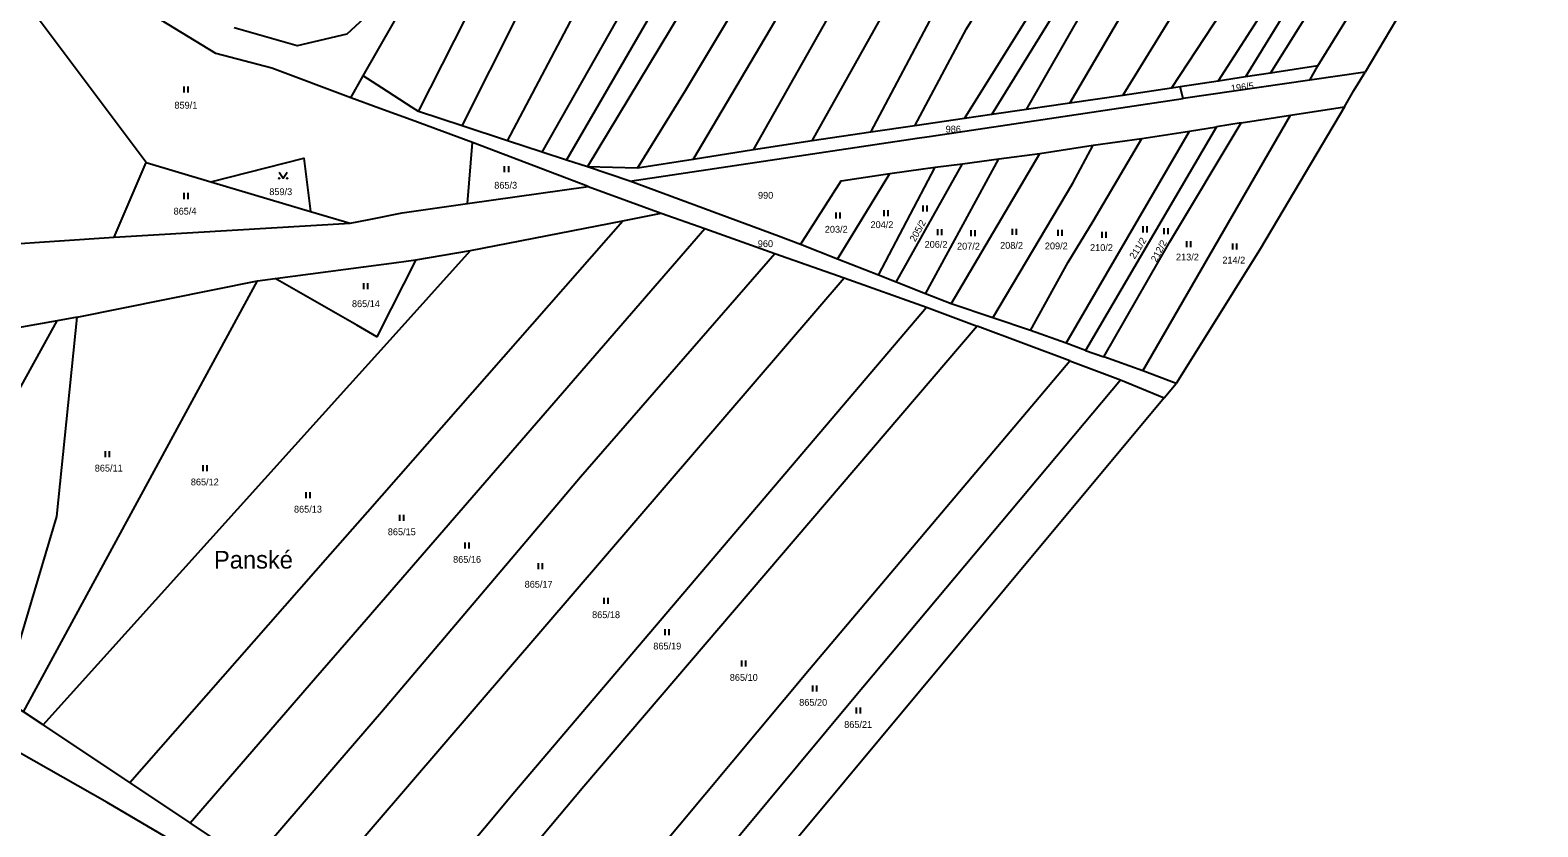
# Model space of a CAD drawing. Extents: x -751333 to -746055, y -1133395 to -1129777.
# Drawn here: x -747223.3 to -746848.3, y -1131915.2 to -1131717 of the extents above; entities that cross this region are included whole.
import ezdxf

# ---------------------------------------------------------------- set-up
doc = ezdxf.new("R2010")
doc.units = 0
for name, color, linetype in [('Hranice parcel', 7, 'Continuous'), ('Parcelní čísla', 7, 'Continuous'), ('Pop  PČ popisy', 7, 'Continuous'), ('Značky kultur', 7, 'Continuous')]:
    doc.layers.add(name, color=color, linetype=linetype)

msp = doc.modelspace()

# ---------------------------------------------------------------- linework, layer by layer
at = {"layer": 'Hranice parcel'}
for p, q in [((-747140.43, -1131728.4), (-747107.8, -1131671.12)), ((-747143.51, -1131733.86), (-747140.43, -1131728.4)), ((-746921.02, -1131728.67), (-746927.75, -1131729.7)), ((-746914.77, -1131727.71), (-746921.02, -1131728.67)), ((-746902.98, -1131725.91), (-746914.77, -1131727.71)), ((-746904.95, -1131729.44), (-746902.98, -1131725.91)), ((-746891.21, -1131727.46), (-746904.95, -1131729.44)), ((-746939.41, -1131731.47), (-746951.49, -1131733.25)), ((-746937.21, -1131731.15), (-746939.41, -1131731.47)), ((-746927.75, -1131729.7), (-746937.21, -1131731.15)), ((-746936.48, -1131734), (-746937.21, -1131731.15)), ((-746904.95, -1131729.44), (-746936.48, -1131734)), ((-746951.49, -1131733.25), (-746964.66, -1131735.18)), ((-746909.81, -1131738.2), (-746896.34, -1131736.09)), ((-747115.85, -1131740.82), (-747126.73, -1131737.25)), ((-746990.85, -1131739.02), (-747003.2, -1131740.83)), ((-746984.07, -1131738.03), (-746990.85, -1131739.02)), ((-746975.44, -1131736.76), (-746984.07, -1131738.03)), ((-746946.5, -1131801.74), (-746909.81, -1131738.2)), ((-746922.05, -1131740.11), (-746928.22, -1131741.07)), ((-746922.05, -1131740.11), (-746909.81, -1131738.2)), ((-747104.57, -1131744.53), (-747115.85, -1131740.82)), ((-747014.2, -1131742.44), (-747028.78, -1131744.58)), ((-747003.2, -1131740.83), (-747014.2, -1131742.44)), ((-746965.61, -1131794.89), (-746934.95, -1131742.12)), ((-746928.22, -1131741.07), (-746960.81, -1131796.68)), ((-746946.77, -1131743.96), (-746934.95, -1131742.12)), ((-746934.95, -1131742.12), (-746928.22, -1131741.07)), ((-747114.55, -1131760.12), (-747113.28, -1131744.96)), ((-747084.49, -1131755.95), (-747113.28, -1131744.96)), ((-747095.98, -1131747.35), (-747104.57, -1131744.53)), ((-747089.88, -1131749.36), (-747095.98, -1131747.35)), ((-747043.35, -1131746.83), (-747058.42, -1131749.2)), ((-747028.78, -1131744.58), (-747043.35, -1131746.83)), ((-746972.15, -1131747.7), (-746958.91, -1131745.66)), ((-746958.91, -1131745.66), (-746946.77, -1131743.96)), ((-747202.38, -1131768.48), (-747194.42, -1131749.94)), ((-747194.42, -1131749.94), (-747178.35, -1131754.73)), ((-747084.67, -1131751), (-747089.88, -1131749.36)), ((-747074.14, -1131754.55), (-747084.67, -1131751)), ((-747072.25, -1131751.38), (-747084.67, -1131751)), ((-747058.42, -1131749.2), (-747072.25, -1131751.38)), ((-747012.31, -1131777.98), (-746998.16, -1131751.1)), ((-747007.84, -1131779.73), (-746991.41, -1131750.26)), ((-747000.55, -1131782.6), (-746982.37, -1131749)), ((-746998.16, -1131751.1), (-746991.41, -1131750.26)), ((-746994.24, -1131785.11), (-746972.15, -1131747.7)), ((-746991.41, -1131750.26), (-746982.37, -1131749)), ((-746982.37, -1131749), (-746972.15, -1131747.7)), ((-747178.35, -1131754.73), (-747153.61, -1131762.1)), ((-747022.48, -1131773.99), (-747009.45, -1131752.7)), ((-747114.55, -1131760.12), (-747084.49, -1131755.95)), ((-747084.49, -1131755.95), (-747066.3, -1131762.59)), ((-747153.61, -1131762.1), (-747143.72, -1131765.05)), ((-747075.87, -1131764.45), (-747066.3, -1131762.59)), ((-747066.3, -1131762.59), (-747055.5, -1131766.4)), ((-747202.38, -1131768.48), (-747143.72, -1131765.05)), ((-747113.75, -1131771.83), (-747075.87, -1131764.45)), ((-747055.5, -1131766.4), (-747038.09, -1131772.55)), ((-747127.4, -1131774.15), (-747113.75, -1131771.83)), ((-747038.09, -1131772.55), (-747020.83, -1131778.66)), ((-747022.48, -1131773.99), (-747031.69, -1131770.37)), ((-747012.31, -1131777.98), (-747022.48, -1131773.99)), ((-747224.99, -1131886.58), (-747166.79, -1131779.35)), ((-747211.65, -1131788.43), (-747166.79, -1131779.35)), ((-747166.79, -1131779.35), (-747162.4, -1131778.78)), ((-747020.83, -1131778.66), (-747000.3, -1131785.93)), ((-747007.84, -1131779.73), (-747012.31, -1131777.98)), ((-747000.55, -1131782.6), (-747007.84, -1131779.73)), ((-746994.24, -1131785.11), (-747000.55, -1131782.6)), ((-746983.84, -1131788.6), (-746994.24, -1131785.11)), ((-747211.65, -1131788.43), (-747216.62, -1131789.31)), ((-747000.3, -1131785.93), (-746987.72, -1131790.65)), ((-746974.46, -1131791.75), (-746983.84, -1131788.6)), ((-747229.61, -1131813), (-747216.62, -1131789.31)), ((-746964.65, -1131799.29), (-746987.72, -1131790.65)), ((-746965.61, -1131794.89), (-746974.46, -1131791.75)), ((-746960.81, -1131796.68), (-746965.61, -1131794.89)), ((-746931.04, -1131793.38), (-746938.23, -1131804.89)), ((-746964.65, -1131799.29), (-746952.09, -1131804)), ((-746960.81, -1131796.68), (-746956.26, -1131798.27)), ((-746946.5, -1131801.74), (-746956.26, -1131798.27)), ((-746938.23, -1131804.89), (-746946.5, -1131801.74)), ((-746952.09, -1131804), (-746941.23, -1131808.49)), ((-746941.23, -1131808.49), (-746938.23, -1131804.89)), ((-746941.23, -1131808.49), (-747020.64, -1131903.85)), ((-747220.07, -1131889.85), (-747224.99, -1131886.58)), ((-747198.55, -1131904.18), (-747220.07, -1131889.85)), ((-747183.54, -1131914.17), (-747198.55, -1131904.18)), ((-747168.35, -1131924.28), (-747183.54, -1131914.17))]:
    msp.add_line(p, q, dxfattribs=at)
for points in [[(-747115.85, -1131740.82), (-747101.98, -1131713.33), (-747085.53, -1131682.34), (-747070.66, -1131651.81), (-747069.92, -1131650.29), (-747060.11, -1131630.3), (-747055.87, -1131622.19), (-747047.5, -1131606.16), (-747025.18, -1131564.19), (-746984.84, -1131493.86), (-746972.78, -1131477.2), (-746949.19, -1131444.14), (-746924.52, -1131406.32), (-746891.3, -1131355.07), (-746872.46, -1131327.44)], [(-747104.57, -1131744.53), (-747074.01, -1131686.66), (-747062.86, -1131663.99), (-747044.55, -1131625.9), (-747038.23, -1131613.87), (-747033.2, -1131604.29), (-747020.87, -1131581.25), (-747014.2, -1131568.8), (-746980.89, -1131511.72), (-746959.19, -1131477.95), (-746938.3, -1131445.7), (-746906.3, -1131397.79), (-746880.95, -1131356.37), (-746864.98, -1131331.78)], [(-747095.98, -1131747.35), (-747074.34, -1131709.19), (-747062.94, -1131688.91), (-747054.44, -1131671.18), (-747030.22, -1131622.02), (-747003.78, -1131573.59), (-746999.79, -1131566.27), (-746985.12, -1131541.69), (-746979.78, -1131532.75), (-746975.21, -1131525.11), (-746953.97, -1131491.61), (-746897.43, -1131402.02), (-746856.2, -1131336.86)], [(-747089.88, -1131749.36), (-747056.78, -1131692.26), (-747040.44, -1131657.76), (-747010.02, -1131596.06), (-746982.14, -1131547.97), (-746977.6, -1131540.14), (-746952.97, -1131500.95), (-746943.76, -1131486.29), (-746932.5, -1131468.46), (-746900.9, -1131419.92), (-746886.76, -1131396.86), (-746861.19, -1131356.24), (-746848.88, -1131337.27)], [(-747084.67, -1131751), (-747056.2, -1131703.86), (-747037.38, -1131665.4), (-747027.75, -1131645.14), (-747010.19, -1131608.84), (-747001.37, -1131592.36), (-746984.88, -1131564.32), (-746959.67, -1131522.76), (-746955.95, -1131516.9), (-746940.13, -1131491.96), (-746923.29, -1131465.74), (-746918.73, -1131458.64), (-746886.86, -1131408.57), (-746872, -1131384.8), (-746844.5, -1131337.51)], [(-747072.25, -1131751.38), (-747060.28, -1131732), (-747039.59, -1131697.38), (-747028.61, -1131673.06), (-747010.61, -1131638.67), (-746991.07, -1131601.65), (-746978.19, -1131579.68), (-746954.07, -1131538.52), (-746930.93, -1131499.45), (-746914.81, -1131473.69), (-746900.96, -1131451.69), (-746895.63, -1131443.23), (-746877.35, -1131414.14), (-746871.32, -1131404.39), (-746861.32, -1131388.21), (-746832.31, -1131338.23)], [(-747058.42, -1131749.2), (-747038.09, -1131714.85), (-747017.02, -1131676.4), (-746987.05, -1131621.46), (-746963.1, -1131578.77), (-746922.22, -1131508.08), (-746895.58, -1131462.61), (-746885.22, -1131445.58), (-746861.28, -1131407.04), (-746857.11, -1131399.99), (-746832.67, -1131358.76), (-746821.13, -1131339.58)], [(-747043.35, -1131746.83), (-747012.7, -1131692.42), (-747004.53, -1131676.4), (-746988.51, -1131647.63), (-746951.39, -1131581.85), (-746924.23, -1131534.57), (-746904.03, -1131500.8), (-746883.99, -1131466.86), (-746842.36, -1131398.13), (-746824.55, -1131367.37), (-746811.66, -1131346), (-746808.72, -1131341.12)], [(-747028.78, -1131744.58), (-747015.65, -1131721.17), (-746994.33, -1131683.03), (-746980.83, -1131659.61), (-746963.82, -1131630.88), (-746947.17, -1131601.52), (-746919.98, -1131553.97), (-746908.36, -1131532.89), (-746893.15, -1131504.79), (-746883.53, -1131486.51), (-746871.73, -1131466.88), (-746842.83, -1131420.22), (-746814.47, -1131369.41), (-746798.54, -1131343.8)], [(-747014.2, -1131742.44), (-746998.02, -1131711.91), (-746986.84, -1131694.8), (-746954.43, -1131638.96), (-746913.55, -1131568.61), (-746875.82, -1131496.38), (-746844.04, -1131445.67), (-746820.17, -1131403.25), (-746804.23, -1131373.45), (-746788.13, -1131346.53)], [(-747003.2, -1131740.83), (-746990.36, -1131716.69), (-746969.83, -1131683.37), (-746954.44, -1131658.33), (-746938.41, -1131630.76), (-746907.08, -1131576), (-746881.78, -1131529.17), (-746860.71, -1131491.16), (-746828.65, -1131435.77), (-746803.15, -1131391.01), (-746779.33, -1131348.85)], [(-746990.85, -1131739.02), (-746967.01, -1131700.7), (-746944.49, -1131660.79), (-746927.2, -1131631.17), (-746901.46, -1131584.95), (-746872.72, -1131533.26), (-746835.26, -1131467.04), (-746805.54, -1131414.43), (-746786.36, -1131381.65), (-746769.23, -1131352.27)], [(-746984.07, -1131738.03), (-746956.76, -1131693.62), (-746930.93, -1131647.96), (-746900.47, -1131595.76), (-746868.27, -1131537.95), (-746830.68, -1131470.71), (-746810.85, -1131435.82), (-746776.73, -1131375.73), (-746764.19, -1131354.41)], [(-746975.44, -1131736.76), (-746951.32, -1131694.53), (-746914.93, -1131630.57), (-746896.94, -1131599.81), (-746888.97, -1131584.23), (-746874.92, -1131559.39), (-746854.79, -1131524.52), (-746827.75, -1131476.66), (-746792.97, -1131415.79), (-746773.98, -1131382.51), (-746758.48, -1131357.76)], [(-746964.66, -1131735.18), (-746937.82, -1131689.24), (-746909.87, -1131639.48), (-746895.97, -1131615.54), (-746872.27, -1131573.98), (-746850.31, -1131536.07), (-746831.17, -1131502.49), (-746808.23, -1131462.22), (-746792.36, -1131433.87), (-746763.35, -1131382.36), (-746749.89, -1131362.79)], [(-746951.49, -1131733.25), (-746931.91, -1131701.47), (-746888.6, -1131625.72), (-746854.73, -1131563.34), (-746833.09, -1131523.91), (-746818.81, -1131499.06), (-746785.31, -1131439.88), (-746759.87, -1131395.96), (-746741.44, -1131367.75)], [(-746939.41, -1131731.47), (-746922.78, -1131706.16), (-746885.19, -1131638.39), (-746862.7, -1131598.42), (-746843.79, -1131566.28), (-746817.59, -1131520.32), (-746790.54, -1131471.76), (-746755.61, -1131410.4), (-746732.32, -1131373.1)], [(-746927.75, -1131729.7), (-746911.51, -1131704.41), (-746890.72, -1131669.08), (-746852.43, -1131600.31), (-746825.91, -1131552.9), (-746799.17, -1131506.71), (-746783.9, -1131480.65), (-746743.56, -1131407.78), (-746725.23, -1131377.02)], [(-746719.96, -1131379.93), (-746754.34, -1131438.63), (-746789.74, -1131501.01), (-746804.77, -1131526.77), (-746817.08, -1131549.42), (-746845.95, -1131600.18), (-746871.48, -1131645.69), (-746889.1, -1131676.85), (-746895.02, -1131686.35), (-746921.02, -1131728.67)], [(-746914.77, -1131727.71), (-746899.96, -1131704.06), (-746890.46, -1131686.35), (-746873.6, -1131657.79), (-746841.77, -1131601.25), (-746803.56, -1131534.6), (-746785.77, -1131503.44), (-746759.79, -1131458.77), (-746727.58, -1131402.99), (-746716.03, -1131382.11)], [(-746902.98, -1131725.91), (-746875.56, -1131681.48), (-746856.95, -1131647.82), (-746831.81, -1131603.9), (-746823.76, -1131588.48), (-746792.61, -1131535.89), (-746783.34, -1131518.48), (-746771.27, -1131499.19), (-746735.03, -1131436.04), (-746706.95, -1131387.13)], [(-746698.14, -1131392), (-746721.13, -1131432.18), (-746762.97, -1131504.51), (-746805.6, -1131577.83), (-746835.31, -1131629.56), (-746853.4, -1131661.11), (-746880.17, -1131708.85), (-746891.21, -1131727.46)], [(-747126.73, -1131737.25), (-747102.71, -1131689.93), (-747094.62, -1131674), (-747086.88, -1131658.52), (-747076.71, -1131638.17), (-747059.66, -1131599.64)], [(-747194.42, -1131749.94), (-747242.32, -1131686.21), (-747246.06, -1131670.63)], [(-747143.51, -1131733.86), (-747163.2, -1131726.49), (-747177.09, -1131722.8), (-747200.93, -1131708.24), (-747246.06, -1131670.63)], [(-747129.15, -1131700.25), (-747135, -1131709.19), (-747144.51, -1131718.02), (-747156.9, -1131720.96), (-747172.52, -1131716.41)], [(-747126.73, -1131737.25), (-747128.24, -1131736.28), (-747135.85, -1131731.36), (-747140.43, -1131728.4)], [(-746896.34, -1131736.09), (-746894.04, -1131732), (-746891.21, -1131727.46)], [(-747113.28, -1131744.96), (-747128.51, -1131739.37), (-747136.3, -1131736.51), (-747143.51, -1131733.86)], [(-747074.14, -1131754.55), (-747002.66, -1131743.88), (-746999.69, -1131743.44), (-746936.48, -1131734)], [(-746964.66, -1131735.18), (-746970.96, -1131736.1), (-746975.44, -1131736.76)], [(-746896.34, -1131736.09), (-746917.25, -1131771.33), (-746931.04, -1131793.38)], [(-746956.26, -1131798.27), (-746939.82, -1131769.7), (-746922.05, -1131740.11)], [(-746983.84, -1131788.6), (-746963.95, -1131755.12), (-746958.91, -1131745.66)], [(-746974.46, -1131791.75), (-746965.07, -1131774.75), (-746958.86, -1131764.57), (-746946.77, -1131743.96)], [(-747178.35, -1131754.73), (-747155.26, -1131748.88), (-747153.61, -1131762.1)], [(-747009.45, -1131752.7), (-747001.14, -1131751.51), (-746998.16, -1131751.1)], [(-747031.69, -1131770.37), (-747037.13, -1131768.24), (-747074.14, -1131754.55)], [(-747031.69, -1131770.37), (-747021.54, -1131754.52), (-747009.45, -1131752.7)], [(-747143.72, -1131765.05), (-747138.98, -1131764.12), (-747130.74, -1131762.5), (-747114.55, -1131760.12)], [(-747267.01, -1131766.16), (-747244.55, -1131771.35), (-747202.38, -1131768.48)], [(-747198.55, -1131904.18), (-747148.7, -1131847.4), (-747139.41, -1131836.82), (-747075.87, -1131764.45)], [(-747183.54, -1131914.17), (-747152.3, -1131878.12), (-747142.97, -1131867.35), (-747055.5, -1131766.4)], [(-747220.07, -1131889.85), (-747143.77, -1131805.15), (-747134.52, -1131794.88), (-747113.75, -1131771.83)], [(-747168.35, -1131924.28), (-747156.17, -1131910.12), (-747146.8, -1131899.23), (-747135.89, -1131886.55), (-747102.76, -1131847.44), (-747086.37, -1131828.14), (-747038.09, -1131772.55)], [(-747127.4, -1131774.15), (-747133.52, -1131786.29), (-747137.05, -1131793.3), (-747142.05, -1131790.43), (-747162.4, -1131778.78)], [(-747162.4, -1131778.78), (-747140.35, -1131775.86), (-747132.18, -1131774.78), (-747127.4, -1131774.15)], [(-747154.03, -1131933.81), (-747087.71, -1131856.54), (-747020.83, -1131778.66)], [(-747216.62, -1131789.31), (-747232.12, -1131792.08), (-747249.62, -1131788.14)], [(-747224.99, -1131886.58), (-747230.08, -1131883.19), (-747216.68, -1131837.99), (-747213.89, -1131810.39), (-747211.65, -1131788.43)], [(-747132.91, -1131942.59), (-747102.75, -1131906.39), (-747000.3, -1131785.93)], [(-746987.72, -1131790.65), (-747085.59, -1131905.13), (-747118.82, -1131944.76)], [(-747094.15, -1131953.41), (-747029.41, -1131875.97), (-746964.65, -1131799.29)], [(-747081.82, -1131959.38), (-747018.32, -1131883), (-746952.09, -1131804)], [(-747072.89, -1131966.47), (-747107.18, -1131952.81), (-747140.46, -1131946.56), (-747154.1, -1131938.56), (-747161.04, -1131934.49), (-747204.18, -1131909.18), (-747226.07, -1131896.73), (-747265.2, -1131885.54)], [(-747020.64, -1131903.85), (-747058.92, -1131949.83), (-747071.24, -1131964.51)]]:
    msp.add_lwpolyline(points, dxfattribs=at)
at = {"layer": 'Značky kultur'}
for p, q in [((-747185.011, -1131732.52), (-747185.011, -1131731.02)), ((-747184.01, -1131732.52), (-747184.01, -1131731.02)), ((-747105.271, -1131752.35), (-747105.271, -1131750.85)), ((-747104.27, -1131752.35), (-747104.27, -1131750.85)), ((-747185.031, -1131759.03), (-747185.031, -1131757.53)), ((-747184.03, -1131759.03), (-747184.03, -1131757.53)), ((-747022.781, -1131763.86), (-747022.781, -1131762.36)), ((-747021.78, -1131763.86), (-747021.78, -1131762.36)), ((-747010.881, -1131763.27), (-747010.881, -1131761.77)), ((-747009.88, -1131763.27), (-747009.88, -1131761.77)), ((-747001.191, -1131762.13), (-747001.191, -1131760.63)), ((-747000.19, -1131762.13), (-747000.19, -1131760.63)), ((-746946.451, -1131767.32), (-746946.451, -1131765.82)), ((-746945.45, -1131767.32), (-746945.45, -1131765.82)), ((-746941.181, -1131767.79), (-746941.181, -1131766.29)), ((-746940.18, -1131767.79), (-746940.18, -1131766.29)), ((-746997.551, -1131768.04), (-746997.551, -1131766.54)), ((-746996.55, -1131768.04), (-746996.55, -1131766.54)), ((-746989.201, -1131768.25), (-746989.201, -1131766.75)), ((-746988.2, -1131768.25), (-746988.2, -1131766.75)), ((-746978.971, -1131767.92), (-746978.971, -1131766.42)), ((-746977.97, -1131767.92), (-746977.97, -1131766.42)), ((-746967.551, -1131768.16), (-746967.551, -1131766.66)), ((-746966.55, -1131768.16), (-746966.55, -1131766.66)), ((-746956.631, -1131768.66), (-746956.631, -1131767.16)), ((-746955.63, -1131768.66), (-746955.63, -1131767.16)), ((-746935.571, -1131771.01), (-746935.571, -1131769.51)), ((-746934.57, -1131771.01), (-746934.57, -1131769.51)), ((-746924.101, -1131771.59), (-746924.101, -1131770.09)), ((-746923.1, -1131771.59), (-746923.1, -1131770.09)), ((-747140.281, -1131781.49), (-747140.281, -1131779.99)), ((-747139.28, -1131781.49), (-747139.28, -1131779.99)), ((-747204.561, -1131823.27), (-747204.561, -1131821.77)), ((-747203.56, -1131823.27), (-747203.56, -1131821.77)), ((-747180.291, -1131826.71), (-747180.291, -1131825.21)), ((-747179.29, -1131826.71), (-747179.29, -1131825.21)), ((-747154.621, -1131833.48), (-747154.621, -1131831.98)), ((-747153.62, -1131833.48), (-747153.62, -1131831.98)), ((-747131.321, -1131839.1), (-747131.321, -1131837.6)), ((-747130.32, -1131839.1), (-747130.32, -1131837.6)), ((-747115.111, -1131845.97), (-747115.111, -1131844.47)), ((-747114.11, -1131845.97), (-747114.11, -1131844.47)), ((-747096.871, -1131851.14), (-747096.871, -1131849.64)), ((-747095.87, -1131851.14), (-747095.87, -1131849.64)), ((-747080.511, -1131859.73), (-747080.511, -1131858.23)), ((-747079.51, -1131859.73), (-747079.51, -1131858.23)), ((-747065.321, -1131867.53), (-747065.321, -1131866.03)), ((-747064.32, -1131867.53), (-747064.32, -1131866.03)), ((-747046.261, -1131875.33), (-747046.261, -1131873.83)), ((-747045.26, -1131875.33), (-747045.26, -1131873.83)), ((-747028.621, -1131881.53), (-747028.621, -1131880.03)), ((-747027.62, -1131881.53), (-747027.62, -1131880.03)), ((-747017.761, -1131887.03), (-747017.761, -1131885.53)), ((-747016.76, -1131887.03), (-747016.76, -1131885.53))]:
    msp.add_line(p, q, dxfattribs=at)
msp.add_lwpolyline([(-747161.36, -1131752.379), (-747160.36, -1131753.88), (-747159.36, -1131752.379)], dxfattribs=at)
for centre in [(-747161.36, -1131753.879), (-747159.36, -1131753.879)]:
    msp.add_circle(centre, 0.1, dxfattribs=at)

# ---------------------------------------------------------------- texts
at = {"layer": 'Parcelní čísla'}
for s, rotation, p in [('196/5', 7, (-746924.486, -1131732.353)), ('205/2', 61, (-747003.146, -1131769.812)), ('211/2', 58, (-746948.549, -1131774.1)), ('212/2', 62, (-746943.129, -1131774.829))]:
    msp.add_text(s, height=1.7, rotation=rotation, dxfattribs=at).set_placement(p)
for s, p in [('859/1', (-747187.42, -1131736.55)), ('986', (-746995.57, -1131742.49)), ('865/3', (-747107.86, -1131756.46)), ('859/3', (-747163.82, -1131758.06)), ('990', (-747042.25, -1131758.96)), ('865/4', (-747187.63, -1131762.91)), ('203/2', (-747025.63, -1131767.41)), ('204/2', (-747014.26, -1131766.26)), ('960', (-747042.3, -1131770.99)), ('206/2', (-747000.81, -1131771.16)), ('207/2', (-746992.74, -1131771.61)), ('208/2', (-746982.02, -1131771.41)), ('209/2', (-746970.89, -1131771.55)), ('210/2', (-746959.65, -1131771.96)), ('213/2', (-746938.27, -1131774.31)), ('214/2', (-746926.73, -1131775.07)), ('865/14', (-747143.26, -1131785.92)), ('865/11', (-747207.24, -1131826.82)), ('865/12', (-747183.34, -1131830.26)), ('865/13', (-747157.68, -1131837.03)), ('865/15', (-747134.34, -1131842.65)), ('865/16', (-747118.1, -1131849.52)), ('865/17', (-747100.3, -1131855.71)), ('865/18', (-747083.52, -1131863.28)), ('865/19', (-747068.3, -1131871.08)), ('865/10', (-747049.27, -1131878.88)), ('865/20', (-747032, -1131885.08)), ('865/21', (-747020.81, -1131890.58))]:
    msp.add_text(s, height=1.7, dxfattribs=at).set_placement(p)
at = {"layer": 'Pop  PČ popisy'}
msp.add_text('Panské', height=4.4, dxfattribs=at).set_placement((-747177.575, -1131850.95))

doc.saveas('drawing.dxf')
